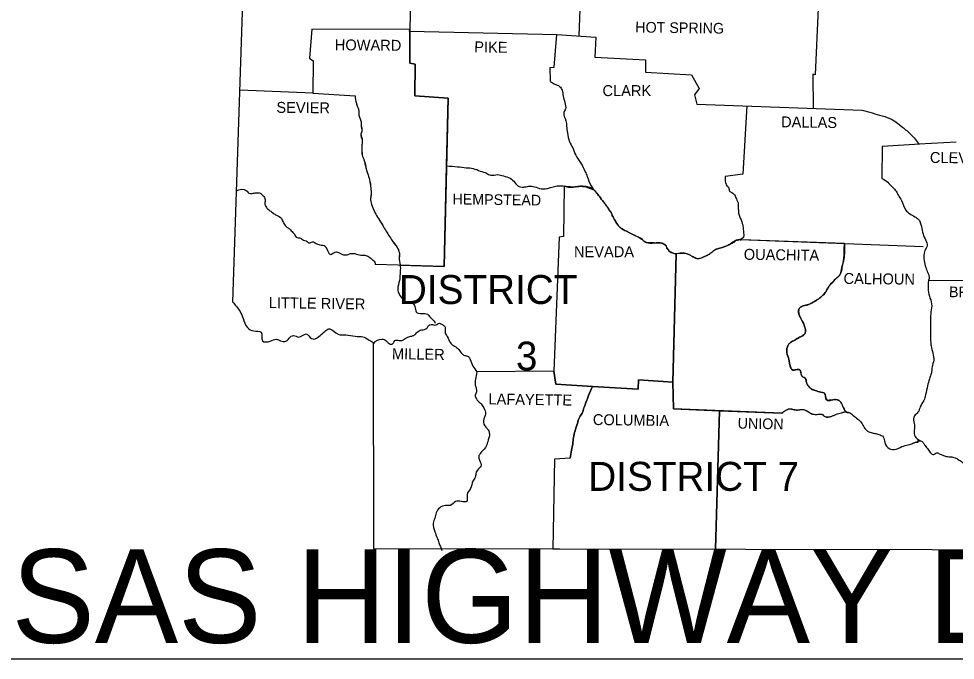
# Model space of a CAD drawing. Extents: x -24122 to 24238, y -8840 to 11381.
# Drawn here: x 10036 to 13643, y 4654 to 7122 of the extents above; entities that cross this region are included whole.
import ezdxf

# ---------------------------------------------------------------- set-up
doc = ezdxf.new("R2010")
doc.units = 0
for name, color, linetype in [('R_Annotation', 7, 'Continuous'), ('R_Border', 7, 'Continuous'), ('R_Grid', 7, 'Continuous'), ('S_AREA_CALC', 7, 'Continuous')]:
    doc.layers.add(name, color=color, linetype=linetype)

msp = doc.modelspace()

# ---------------------------------------------------------------- linework, layer by layer
at = {"layer": 'R_Annotation'}
for p, q in [((11541.8, 7081.3), (11165.1, 7082.3)), ((11541.7, 7074.5), (11541.8, 7081.3)), ((11541.8, 7074.5), (11541.7, 7074.5)), ((11170, 6961), (11169, 6835.7)), ((11169, 6835.7), (11331.5, 6825.9)), ((11684.2, 6556.2), (11684.2, 6556.2)), ((12568.2, 6217.4), (12555.3, 5724.3)), ((12557.4, 5620.5), (12555.3, 5724.3)), ((12735.5, 5613.9), (12557.4, 5620.5)), ((12720, 5081.2), (12735.5, 5613.9)), ((12092.7, 5082.3), (12720, 5081.2))]:
    msp.add_line(p, q, dxfattribs=at)
for points in [[(11165.1, 7082.3), (11156.3, 6970.8), (11170, 6961)], [(11684.2, 6556.2), (11690.5, 6816.2), (11561.4, 6825.9), (11563.3, 6947.3), (11541.8, 6951.2), (11541.8, 7074.5)], [(11505.4, 6173.8), (11674.9, 6169.4), (11684.2, 6556.2)], [(11684.2, 6556.2), (11684.2, 6556.2)], [(12136.7, 6478.1), (12134.7, 6283.9), (12117.1, 6282), (12097.5, 5766.3)], [(13216.3, 6257.6), (13216.3, 6257.6), (12819.4, 6272)], [(12246.3, 5707.6), (12422.4, 5696.9), (12423.4, 5733.1), (12555.3, 5724.3), (12568.2, 6217.4)], [(12097.5, 5766.3), (12104.4, 5715.5), (12246.3, 5707.6)], [(12555.3, 5724.3), (12423.4, 5733.1), (12422.4, 5696.9), (12246.3, 5707.6)], [(12555.3, 5724.3), (12557.4, 5620.5), (12735.5, 5613.9), (12975.2, 5604.9)], [(12160.2, 5430.7), (12099.5, 5426.8), (12092.7, 5082.4)], [(12092.7, 5082.4), (12092.7, 5082.3)]]:
    msp.add_lwpolyline(points, dxfattribs=at)
for points in [[(11331.5, 6825.9), (11336.3, 6796.6), (11338.2, 6790.1), (11340.7, 6783.8), (11343.2, 6777.6), (11345.2, 6771.2), (11345.7, 6766.3), (11345.8, 6761.4), (11345.7, 6756.4), (11346.1, 6751.6), (11348.1, 6744.2), (11350.8, 6737), (11353.4, 6729.7), (11354.9, 6722.2), (11354.9, 6711.5), (11355.5, 6706.1), (11356.4, 6700.7), (11357.3, 6695.3), (11357.9, 6689.9), (11357.3, 6687), (11356, 6684.1), (11354.6, 6681.2), (11354, 6678.2), (11354.8, 6672.4), (11356.5, 6666.6), (11358.2, 6660.7), (11358.9, 6654.7), (11357.9, 6637.1), (11357.9, 6622.4), (11358, 6610.2), (11358.3, 6604.1), (11358.9, 6598), (11360.2, 6592.4), (11362.4, 6587.1), (11364.8, 6581.9), (11366.7, 6576.5), (11370.5, 6560.3), (11374.5, 6544.2), (11379.4, 6527.5), (11387.2, 6502.1), (11392.1, 6470.8), (11393.1, 6447.3), (11392.8, 6441.9), (11392, 6436.5), (11391.3, 6431.2), (11391.1, 6425.8), (11397, 6401.3), (11407.8, 6376.9), (11421.5, 6353.4), (11426.8, 6344.8)], [(12251.7, 6464.2), (12239.4, 6471), (12226.6, 6475.2), (12213.5, 6477.3), (12200.3, 6477.6), (12193.2, 6477.1), (12186.1, 6476.1), (12179, 6475.1), (12171.9, 6474.7), (12159.7, 6474.9), (12147.4, 6475.7), (12142, 6476.7), (12136.7, 6478.1)], [(11426.8, 6344.8), (11438.1, 6327), (11449.8, 6306.4), (11464.5, 6283.9), (11476.3, 6265.3), (11480.5, 6259.3), (11485, 6253.6), (11489.5, 6247.9), (11493.9, 6241.8), (11501.7, 6222.3), (11502.1, 6215.4), (11501.9, 6208.6), (11501.5, 6201.7), (11501.7, 6194.9), (11502.5, 6189.6), (11503.5, 6184.3), (11505.4, 6173.8)], [(12814.7, 6272.2), (12813.6, 6272.2), (12812.4, 6272.1), (12810.1, 6272), (12805.4, 6271.3), (12800.8, 6270.1), (12798.4, 6269.2), (12796.1, 6268.3)], [(12819.4, 6272), (12818.5, 6271.4), (12816.2, 6270.6), (12815.2, 6271), (12814.7, 6272.2)], [(13042, 5895.5), (13043.7, 5896.5), (13059.3, 5905.3), (13066.2, 5916), (13066.6, 5920.7), (13066.3, 5925.4), (13065.5, 5930.1), (13064.2, 5934.6), (13058.3, 5950.3), (13054.4, 5958.7), (13050.1, 5967), (13045.7, 5975.2), (13041.7, 5983.5), (13039.2, 5995.3), (13040.1, 6001.3), (13042.7, 6007), (13044.1, 6009), (13045.7, 6010.7), (13049.2, 6013.7), (13057.4, 6017.8), (13062.5, 6019.2), (13067.7, 6020.1), (13072.9, 6021.1), (13077.9, 6022.7), (13096.5, 6031.5), (13113.1, 6041.3), (13129.8, 6055), (13142.5, 6068.7), (13145.9, 6073.9), (13148.9, 6079.4), (13151.8, 6085), (13155.2, 6090.2), (13169.9, 6107.8), (13177.7, 6115.6), (13185.5, 6123.5), (13193.5, 6130.7), (13197.2, 6134.6), (13200.2, 6139.1), (13201, 6140.7), (13201.7, 6142.4), (13202.8, 6145.8), (13204.5, 6152.6), (13207.1, 6166.5), (13211, 6181.6), (13213.9, 6196.8), (13214.6, 6204.4), (13215.1, 6212), (13215.7, 6227.2), (13216.3, 6257.6)], [(13222.8, 5610.2), (13214.9, 5620.5), (13212.5, 5625.4), (13210.5, 5630.3), (13208.4, 5635.3), (13206.1, 5640.1), (13202.5, 5646.4), (13197.3, 5651.9), (13194.9, 5653.4), (13192.5, 5654.6), (13187.6, 5656.3), (13177.7, 5656.8), (13166, 5654.8), (13158.1, 5653.9), (13150.3, 5653.8), (13147.2, 5655.1), (13145.4, 5658.1), (13143.8, 5667.2), (13142.3, 5676.7), (13139.3, 5681.4), (13137.6, 5682.2), (13125.9, 5685.1), (13103.4, 5692), (13092.6, 5695.9), (13084.5, 5701.1), (13081, 5704.6), (13077.9, 5708.6), (13072.8, 5717.7), (13069.1, 5727.2), (13068.5, 5729.6), (13068.2, 5732.1), (13067.8, 5734.6), (13067.1, 5737), (13064.2, 5740.2), (13059.8, 5742.3), (13055.4, 5744.4), (13052.5, 5747.7), (13048.6, 5760.5), (13047.6, 5765.4), (13047.1, 5768), (13045.6, 5770.2), (13044.5, 5770.9), (13043.4, 5771.5), (13041.3, 5772.2), (13036.8, 5772.3), (13032.4, 5771.7), (13030.2, 5771.4), (13028, 5771.2), (13025.6, 5770.8), (13023.1, 5770.1), (13020.7, 5769.7), (13018.2, 5770.2), (13016.6, 5771.2), (13015.2, 5772.3), (13012.7, 5774.8), (13009.2, 5780.9), (13007.1, 5787.7), (13005.5, 5794.7), (13004.7, 5798.6), (13004, 5802.6), (13002.6, 5810.4), (13000.8, 5817), (12998.6, 5823.6), (12996.5, 5830.2), (12994.7, 5836.8), (12994.1, 5848), (12996.7, 5859.3), (12998.8, 5864.2), (13001.3, 5868.8), (13004.5, 5872.8), (13008.4, 5875.9), (13025.1, 5885.7), (13042, 5895.5)], [(12246.3, 5707.6), (12230.6, 5672.4), (12221.8, 5647.9), (12213, 5624.5), (12206.2, 5604.9), (12195.4, 5588.3), (12187.6, 5564.8), (12178.8, 5536.4), (12172.9, 5510), (12170, 5486.5), (12165.1, 5462), (12160.2, 5430.7)], [(12975.2, 5604.9), (12990.8, 5615.7), (13005.5, 5621.5), (13012.8, 5620.3), (13016.5, 5619.3), (13020.2, 5618.6), (13035.8, 5616.6), (13039.3, 5616.8), (13042.7, 5617.5), (13046.1, 5618.2), (13049.5, 5618.6), (13067.1, 5615.7), (13071.1, 5613.7), (13074.7, 5611.3), (13078.2, 5609), (13081.8, 5606.9), (13089.9, 5602.4), (13098.5, 5600), (13115.1, 5600), (13129.8, 5600), (13133.2, 5598.8), (13136.2, 5596), (13139.2, 5593), (13142.5, 5591.2), (13148.3, 5590.4), (13154.3, 5590.2), (13160.2, 5590.7), (13166, 5592.2), (13170.9, 5594.1), (13175.7, 5596.1), (13180.6, 5598.2), (13185.5, 5600), (13205.1, 5605.9), (13222.8, 5610.2)]]:
    msp.add_spline(points, degree=3, dxfattribs=at)
for points in [[(12568.2, 6217.4), (12563.6, 6217.6), (12559, 6219.2), (12554.5, 6221.3), (12547.7, 6224.4), (12542.2, 6228.3), (12536.9, 6233), (12531.8, 6237.5), (12532.7, 6246.2), (12527.1, 6250.6), (12520.8, 6255.6), (12514, 6259.1), (12506.5, 6259.4), (12499, 6259.8), (12491.5, 6259.2), (12484, 6259.4), (12473.9, 6259.7), (12463.8, 6259.2), (12453.7, 6261.4), (12444.2, 6263.5), (12438.8, 6273.8), (12430.2, 6278), (12423.4, 6281.4), (12416.4, 6284.4), (12409.7, 6287.8), (12398.8, 6293.3), (12388.1, 6298.8), (12377.4, 6304.5), (12368.5, 6309.1), (12359.8, 6313.6), (12351.9, 6320.1), (12341.8, 6328.6), (12335.8, 6340.2), (12329.4, 6351.4), (12324.2, 6360.7), (12320.5, 6370.8), (12314.8, 6379.8), (12306.4, 6392.8), (12297.8, 6405.7), (12288.3, 6418), (12278.6, 6430.4), (12268.7, 6442.7), (12259, 6455.1), (12256.6, 6458.2), (12254.1, 6461.2), (12251.7, 6464.2)], [(12796.1, 6268.3), (12788.8, 6259.4), (12780.1, 6255.6), (12770.7, 6251.6), (12764.2, 6248.8), (12757.8, 6246.1), (12751.1, 6243.8), (12746.2, 6242.1), (12741.3, 6240.5), (12736.4, 6238.9), (12731.9, 6237.4), (12727.1, 6237.1), (12722.8, 6235), (12716.3, 6231.8), (12710.9, 6227.3), (12705.1, 6223.2), (12700.5, 6220), (12696.2, 6216.6), (12691.4, 6213.5), (12685.7, 6209.7), (12679.3, 6207.4), (12672.9, 6204.7), (12667, 6202.1), (12661.1, 6199.4), (12655.2, 6198.8), (12648.1, 6198.1), (12640.9, 6202.1), (12633.7, 6205.6), (12629.4, 6207.7), (12626.1, 6210.4), (12622, 6212.5), (12617.9, 6214.5), (12613.6, 6216.2), (12609.3, 6217.4), (12596, 6220.9), (12581.6, 6220.3), (12568.2, 6217.4)]]:
    msp.add_open_spline(points, degree=3, dxfattribs=at)
at = {"layer": 'S_AREA_CALC'}
msp.add_line((8346, 4659.5), (17500, 4659.5), dxfattribs=at)
for points in [[(10745.4, 10313), (10947.9, 8686.9), (10859.9, 6032.5)], [(12215.9, 7670.3), (12193.3, 7056.2)], [(11552.6, 7562.7), (11541.8, 7081.3), (11165.1, 7082.3), (11156.3, 6970.8), (11170, 6961), (11169, 6835.7), (10887, 6848.1)], [(13115.1, 7162.5), (13103.4, 6906.2), (13094.5, 6909.1), (13095.5, 6776)], [(11541.8, 7081.3), (11541.8, 6951.2), (11563.3, 6947.3), (11561.4, 6825.9), (11690.5, 6816.2), (11674.9, 6169.4), (11408.8, 6176.3)], [(11541.7, 7074.5), (12108.3, 7061.7)], [(12084.8, 6880.7), (12082.9, 6934.5), (12098.5, 6935.5), (12108.3, 7061.7), (12259, 7052), (12255.1, 6974.7), (12449.8, 6963.9), (12450.8, 6916.9), (12626.9, 6906.2), (12657.2, 6853.3), (12638.6, 6829.9), (12647.4, 6793.7), (13285.3, 6770.2)], [(11169, 6835.7), (11331.5, 6825.9)], [(12839.9, 6786.6), (12824.5, 6523.6), (12757, 6515.8)], [(13506.5, 6639.1), (13361.7, 6630.3), (13360.7, 6508)], [(13647.3, 6647.9), (13504.5, 6639.1)], [(12136.7, 6478.6), (12134.7, 6283.9), (12117.1, 6282), (12097.5, 5766.3)], [(12814.7, 6272.2), (13219.8, 6257.5), (13520.2, 6245.8)], [(12568.2, 6217.4), (12555.4, 5724.3), (12423.4, 5733.1), (12422.4, 5696.9), (12246.3, 5707.6)], [(13539.7, 6115.6), (13982, 6116.6)], [(11400.9, 5874.9), (11402.9, 5083.4), (14988.7, 5077.5)], [(12246.3, 5707.6), (12104.4, 5715.5), (12097.5, 5766.3), (11801.1, 5763.4)], [(12975.2, 5604.9), (12557.4, 5620.5), (12555.3, 5724.3)], [(12735.5, 5613.9), (12720, 5081.2)], [(12160.2, 5430.7), (12099.5, 5426.8), (12092.7, 5082.4)]]:
    msp.add_lwpolyline(points, dxfattribs=at)
for points in [[(12084.8, 6880.7), (12100.5, 6871), (12119.1, 6862.1), (12128.9, 6847.5), (12132.8, 6825), (12139.6, 6800.5), (12141.6, 6775.1), (12135.7, 6761.4), (12143.5, 6730.1), (12146.5, 6708.5), (12149.4, 6683.1), (12157.2, 6648.9), (12170, 6625.4), (12181.7, 6597), (12201.3, 6566.7), (12217.9, 6533.4), (12225.7, 6515.8), (12240.4, 6479.6), (12259, 6455.1), (12288.3, 6418), (12314.8, 6379.8), (12329.4, 6351.4), (12351.9, 6320.1), (12377.4, 6304.5), (12409.7, 6287.8), (12430.2, 6278), (12453.7, 6261.4), (12484, 6259.4), (12506.5, 6259.4), (12527.1, 6250.6), (12536.9, 6233), (12554.5, 6221.3), (12568.2, 6217.4)], [(11331.5, 6825.9), (11336.3, 6796.6), (11345.2, 6771.2), (11346.1, 6751.6), (11354.9, 6722.2), (11354.9, 6711.5), (11357.9, 6689.9), (11354, 6678.2), (11358.9, 6654.7), (11357.9, 6637.1), (11357.9, 6622.4), (11358.9, 6598), (11366.7, 6576.5), (11374.5, 6544.2), (11379.4, 6527.5), (11387.2, 6502.1), (11392.1, 6470.8), (11393.1, 6447.3), (11391.1, 6425.8), (11397, 6401.3), (11407.8, 6376.9), (11421.5, 6353.4), (11438.1, 6327), (11449.8, 6306.4), (11464.5, 6283.9), (11476.3, 6265.3), (11493.9, 6241.8), (11501.7, 6222.3), (11501.7, 6194.9), (11505.6, 6169.4), (11504.6, 6141.1), (11502.7, 6115.6), (11495.8, 6080.4), (11500.7, 6063.8), (11519.3, 6039.3), (11531.1, 6032.5), (11551.6, 6028.5), (11561.4, 6014.8), (11567.3, 5994.3), (11587.8, 5987.5), (11610.3, 5985.5), (11621.1, 5973.8), (11635.7, 5958.1), (11640.6, 5950.3)], [(13285.3, 6770.2), (13361.7, 6748.7), (13400.8, 6734), (13439.9, 6705.6), (13472.2, 6677.2), (13504.5, 6639.1)], [(11684.2, 6556.2), (11725.8, 6553), (11760, 6549.1), (11786.4, 6546.1), (11813.8, 6536.3), (11838.3, 6527.5), (11853.9, 6520.7), (11880.3, 6522.6), (11902.8, 6517.7), (11928.3, 6508.9), (11946.9, 6492.3), (11958.6, 6479.6), (11981.1, 6474.7), (11999.7, 6477.6), (12022.2, 6475.7), (12047.7, 6467.8), (12068.2, 6468.8), (12084.8, 6472.7), (12104.4, 6477.6), (12128.9, 6479.6), (12147.4, 6475.7), (12171.9, 6474.7), (12200.3, 6477.6), (12253.6, 6462.8)], [(12757, 6515.8), (12757, 6497.2), (12763.8, 6479.6), (12770.7, 6471.8), (12773.6, 6459), (12782.4, 6453.2), (12795.2, 6441.4), (12802, 6424.8), (12806.9, 6414), (12806.9, 6400.3), (12807.9, 6386.6), (12809.8, 6370), (12821.6, 6340.7), (12824.5, 6328.9), (12826.5, 6319.1), (12827.4, 6302.5), (12827.4, 6282.9), (12814.7, 6272.2)], [(13360.7, 6508), (13383.2, 6493.3), (13401.8, 6473.7), (13415.5, 6459), (13424.3, 6442.4), (13436, 6422.8), (13452.6, 6385.7), (13467.3, 6372.9), (13487.9, 6360.2), (13500.6, 6351.4), (13513.3, 6323), (13519.2, 6294.7), (13529.9, 6269.2), (13534.8, 6249.7), (13526, 6230.1), (13524.1, 6191), (13529.9, 6164.5), (13537.8, 6145), (13542.7, 6122.5), (13539.7, 6115.6)], [(10873.8, 6460.3), (10911.7, 6462), (10926.4, 6449.3), (10935.2, 6450.2), (10950.9, 6452.2), (10965.5, 6451.2), (10976.3, 6442.4), (10985.1, 6426.8), (10984.1, 6412.1), (10985.1, 6406.2), (10991.9, 6393.5), (11003.7, 6383.7), (11016.4, 6373.9), (11028.2, 6366.1), (11047.7, 6353.4), (11049.7, 6349.5), (11057.5, 6333.8), (11067.3, 6321.1), (11079, 6313.3), (11091.7, 6299.6), (11097.6, 6293.7), (11107.4, 6280), (11118.2, 6279), (11132.8, 6270.2), (11143.6, 6267.3), (11155.3, 6259.4), (11167.1, 6263.4), (11181.8, 6257.5), (11201.3, 6251.6), (11212.1, 6249.7), (11224.8, 6231.1), (11237.5, 6215.4), (11253.2, 6224.2), (11282.5, 6215.4), (11301.1, 6214.4), (11317.8, 6219.3), (11330.5, 6218.4), (11354, 6212.5), (11368.6, 6212.5), (11384.3, 6206.6), (11399, 6194.9), (11408.8, 6182.2), (11408.8, 6176.3)], [(12796.1, 6268.3), (12770.7, 6251.6), (12751.1, 6243.8), (12736.4, 6238.9), (12722.8, 6235), (12705.1, 6223.2), (12691.4, 6213.5), (12672.9, 6204.7), (12655.2, 6198.8), (12633.7, 6205.6), (12622, 6212.5), (12609.3, 6217.4), (12568.2, 6217.4)], [(12770.7, 6251.6), (12796.1, 6268.3), (12814.7, 6272.2)], [(13216.4, 6257.8), (13213.9, 6196.8), (13207.1, 6166.5), (13200.2, 6139.1), (13185.5, 6123.5), (13169.9, 6107.8), (13155.2, 6090.2), (13142.5, 6068.7), (13129.8, 6055), (13113.1, 6041.3), (13096.5, 6031.5), (13077.9, 6022.7), (13057.4, 6017.8), (13042.7, 6007), (13041.7, 5983.5), (13058.3, 5950.3), (13064.2, 5934.6), (13066.2, 5916), (13059.3, 5905.3), (13043.7, 5896.5), (13025.1, 5885.7), (13008.4, 5875.9), (12996.7, 5859.3), (12994.7, 5836.8), (13002.6, 5810.4), (13005.5, 5794.7), (13018.2, 5770.2), (13028, 5771.2), (13045.6, 5770.2), (13047.6, 5765.4), (13048.6, 5760.5), (13052.5, 5747.7), (13067.1, 5737), (13069.1, 5727.2), (13077.9, 5708.6), (13092.6, 5695.9), (13103.4, 5692), (13125.9, 5685.1), (13137.6, 5682.2), (13150.3, 5653.8), (13166, 5654.8), (13177.7, 5656.8), (13197.3, 5651.9), (13206.1, 5640.1), (13214.9, 5620.5), (13226.6, 5606.9), (13234.5, 5606.9)], [(13539.7, 6115.6), (13543.6, 6055), (13552.4, 6025.6), (13549.5, 5994.3), (13548.5, 5964), (13548.5, 5936.6), (13548.5, 5910.2), (13548.5, 5882.8), (13550.5, 5863.2), (13557.3, 5834.8), (13560.3, 5808.4), (13554.4, 5783), (13551.5, 5759.5), (13543.6, 5736), (13536.8, 5709.6), (13529, 5675.3), (13522.1, 5652.8), (13508.4, 5629.4), (13499.6, 5607.8), (13485.9, 5594.1), (13484, 5570.7), (13486.9, 5549.1), (13484.9, 5529.6), (13491.8, 5511), (13509.4, 5498.2)], [(10859.9, 6032.5), (10888.2, 5995.3), (10900, 5968.9), (10916.6, 5934.6), (10941.1, 5920.9), (10969.4, 5916), (10975.3, 5882.8), (11004.7, 5881.8), (11028.2, 5888.6), (11060.4, 5879.8), (11094.7, 5903.3), (11114.2, 5897.4), (11142.6, 5909.2), (11164.1, 5891.6), (11201.3, 5907.2), (11234.6, 5928.7), (11265.9, 5908.2), (11296.2, 5905.3), (11332.4, 5900.4), (11360.8, 5898.4), (11386.2, 5885.7), (11404.8, 5873), (11400.9, 5874.9)], [(11400.9, 5874.9), (11435.2, 5889.6), (11449.8, 5884.7), (11462.6, 5872), (11477.2, 5872), (11485.1, 5883.7), (11499.7, 5884.7), (11511.5, 5883.7), (11524.2, 5891.6), (11535, 5896.5), (11549.6, 5901.4), (11560.4, 5905.3), (11570.2, 5916), (11587.8, 5924.8), (11608.3, 5931.7), (11614.2, 5941.5), (11624, 5945.4), (11643.6, 5944.4), (11656.3, 5950.3), (11667, 5945.4), (11676.8, 5938.5), (11678.8, 5913.1), (11686.6, 5899.4), (11698.4, 5874.9), (11715, 5862.2), (11730.6, 5849.5), (11736.5, 5841.7), (11753.1, 5827), (11767.8, 5822.1), (11774.7, 5811.3), (11785.4, 5785.9), (11801.1, 5763.4)], [(11801.1, 5763.4), (11795.2, 5735), (11794.2, 5712.5), (11799.1, 5686.1), (11794.2, 5673.4), (11802.1, 5654.8), (11816.7, 5640.1), (11827.5, 5624.5), (11834.4, 5602), (11825.6, 5576.5), (11835.3, 5550.1), (11844.1, 5540.3), (11849, 5524.7), (11842.2, 5494.3), (11833.4, 5471.8), (11813.8, 5449.3), (11807.9, 5438.6), (11810.9, 5423.9), (11815.8, 5400.4), (11810.9, 5393.6), (11798.2, 5376.9), (11794.2, 5358.3), (11785.4, 5342.7), (11775.7, 5314.3), (11762.9, 5290.8), (11761, 5264.4), (11741.4, 5264.4), (11718.9, 5264.4), (11698.4, 5249.7), (11679.8, 5248.8), (11657.3, 5239.9), (11643.6, 5221.4), (11638.7, 5200.8), (11632.8, 5181.2), (11638.7, 5148), (11647.5, 5124.5), (11654.3, 5105.9), (11666.1, 5075.6)], [(12160.2, 5430.7), (12165.1, 5462), (12170, 5486.5), (12172.9, 5510), (12178.8, 5536.4), (12187.6, 5564.8), (12195.4, 5588.3), (12206.2, 5604.9), (12213, 5624.5), (12221.8, 5647.9), (12230.6, 5672.4), (12246.3, 5707.6)], [(12975.2, 5604.9), (12990.8, 5615.7), (13005.5, 5621.5), (13020.2, 5618.6), (13035.8, 5616.6), (13049.5, 5618.6), (13067.1, 5615.7), (13081.8, 5606.9), (13098.5, 5600), (13115.1, 5600), (13129.8, 5600), (13142.5, 5591.2), (13166, 5592.2), (13185.5, 5600), (13205.1, 5605.9), (13231.5, 5608.8), (13255, 5592.2), (13271.6, 5578.5), (13285.3, 5562.8), (13295.1, 5545.2), (13305.9, 5535.4), (13323.5, 5528.6), (13337.2, 5525.6), (13353.8, 5520.8), (13362.6, 5516.8), (13370.5, 5498.2), (13383.2, 5472.8), (13407.6, 5464), (13438, 5475.7), (13462.4, 5482.6), (13480, 5488.5), (13490.8, 5492.4), (13500.6, 5493.4), (13497.6, 5495.3), (13509.4, 5498.2), (13520.2, 5490.4), (13527, 5479.7), (13538.7, 5464), (13549.5, 5450.3), (13560.3, 5445.4), (13571, 5451.3), (13585.7, 5446.4), (13598.4, 5441.5), (13613.1, 5437.6), (13625.8, 5436.6), (13642.5, 5432.7), (13655.2, 5425.8), (13666.9, 5419), (13678.7, 5406.3), (13690.4, 5386.7), (13694.3, 5371.1), (13708, 5355.4), (13720.7, 5355.4), (13739.3, 5330), (13746.2, 5320.2), (13760.8, 5302.6), (13771.6, 5302.6), (13792.1, 5298.7)]]:
    msp.add_spline(points, degree=3, dxfattribs=at)

# ---------------------------------------------------------------- texts
at = {"layer": 'R_Border'}
for s, height, rotation, p in [('HOT SPRING', 41.09, 359.2216, (12410.6, 7069.6)), ('HOWARD', 42.07, 359.5145, (11253.2, 7001.1)), ('PIKE', 42.06, 359.0452, (11790.3, 6993.3)), ('SEVIER', 42.07, 359.4271, (11028.2, 6760.4)), ('DALLAS', 42.06, 359.2462, (12972.2, 6704.6)), ('CLEVELAND', 42.07, 359.3377, (13545.6, 6567.6)), ('HEMPSTEAD', 41.08, 359.1885, (11706.2, 6408.2)), ('OUACHITA', 42.07, 359.2043, (12828.4, 6194.9)), ('CALHOUN', 42.07, 359.3634, (13212.9, 6101.9)), ('BRADLEY', 41.08, 359.1449, (13619, 6051)), ('LITTLE RIVER', 42.073, 359.1697, (10998.8, 6009)), ('MILLER', 42.06, 359.1319, (11473.3, 5812.3)), ('LAFAYETTE', 42.06, 359.1839, (11845.1, 5638.2)), ('COLUMBIA', 42.06, 359.2125, (12247.2, 5558.9)), ('UNION', 41.09, 358.9584, (12804.9, 5545.2))]:
    msp.add_text(s, height=height, rotation=rotation, dxfattribs=at).set_placement(p)
for s, height, p in [('CLARK', 42.07, (12284.6, 6824.7)), ('NEVADA', 42.07, (12174.8, 6204.7)), ('ARKANSAS HIGHWAY DISTRICTS 1, 2, 3, 4, 6, 7 & 9', 360, (8349.3, 4720.5))]:
    msp.add_text(s, height=height, dxfattribs=at).set_placement(p)
at = {"layer": 'R_Grid'}
for s, height, p in [('DISTRICT', 111.54, (11500.2, 6024.5)), ('3', 110.6, (11951.3, 5769.2)), ('DISTRICT 7', 111.54, (12229.6, 5305.5))]:
    msp.add_text(s, height=height, dxfattribs=at).set_placement(p)

doc.saveas('drawing.dxf')
